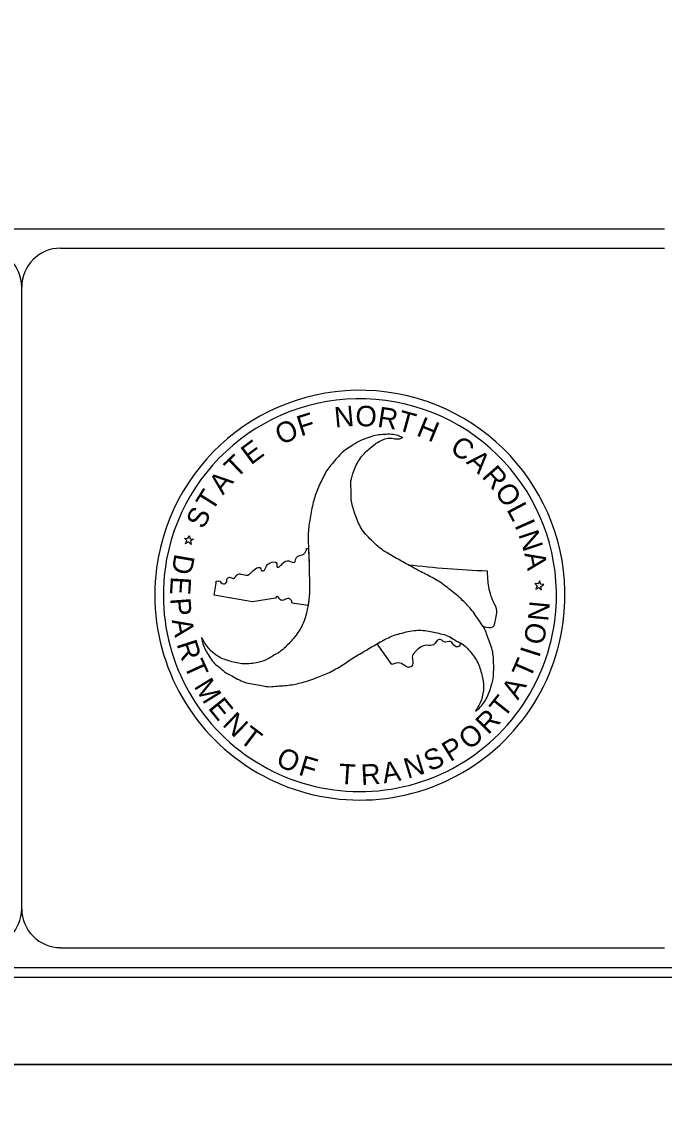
# Model space of a CAD drawing. Extents: x 925297 to 940193, y 663541 to 689899.
# Drawn here: x 937191 to 938513, y 681019 to 683245 of the extents above; entities that cross this region are included whole.
import ezdxf

# ---------------------------------------------------------------- set-up
doc = ezdxf.new("R2010")
doc.units = 0
for name, color, linetype in [('Sheet Cutting Line CELL', 7, 'Continuous'), ('Sheet Plot Border Inside CELL', 7, 'Continuous'), ('Sheet Plot Border Outside CELL', 7, 'Continuous'), ('Sheet Title CELL', 7, 'Continuous')]:
    doc.layers.add(name, color=color, linetype=linetype)

msp = doc.modelspace()

# ---------------------------------------------------------------- linework, layer by layer
at = {"layer": 'Sheet Cutting Line CELL'}
msp.add_line((925296.7, 681098.7), (938768.7, 681098.7), dxfattribs=at)
at = {"layer": 'Sheet Plot Border Inside CELL'}
msp.add_lwpolyline([(925400.7, 681278.2), (938732.7, 681278.2), (938732.7, 689719), (925400.7, 689719)], close=True, dxfattribs=at)
at = {"layer": 'Sheet Plot Border Outside CELL'}
for points in [[(938768.7, 689898.6), (925296.7, 689898.6), (925296.7, 681098.7), (938768.7, 681098.7)], [(925296.7, 672338.7), (938764.7, 672338.7), (938764.7, 681098.7), (925296.7, 681098.7)]]:
    msp.add_lwpolyline(points, close=True, dxfattribs=at)
at = {"layer": 'Sheet Title CELL'}
for p, q in [((927152.7, 682818.7), (938512.7, 682818.7)), ((937270.9, 682778.7), (938512.7, 682778.7)), ((937190.9, 681418.7), (937190.9, 682698.7)), ((937974.9, 682389.9), (937974, 682389.1)), ((937974.9, 682389.9), (937974, 682389.1)), ((937530.7, 682177.1), (937525.5, 682182.2)), ((937525.5, 682182.2), (937532.8, 682181.3)), ((937527.7, 682170.5), (937530.7, 682177.1)), ((937533.8, 682174.1), (937527.7, 682170.5)), ((937532.8, 682181.3), (937535.7, 682187.7)), ((937539.2, 682168.9), (937533.8, 682174.1)), ((937535.7, 682187.7), (937537.2, 682180.7)), ((937537.2, 682180.7), (937544.4, 682179.7)), ((937544.4, 682179.7), (937537.9, 682176.2)), ((937537.9, 682176.2), (937539.2, 682168.9)), ((937985.5, 682127.2), (937985.5, 682127.2)), ((937586.7, 682064.5), (937590.9, 682089.5)), ((938253.2, 682087.8), (938246.1, 682088.7)), ((938246.1, 682088.7), (938251.4, 682083.7)), ((938251.4, 682083.7), (938248.4, 682077.1)), ((938248.4, 682077.1), (938254.6, 682080.6)), ((938256.4, 682094.2), (938253.2, 682087.8)), ((938254.6, 682080.6), (938259.8, 682075.6)), ((938258, 682087.2), (938256.4, 682094.2)), ((938265, 682086.5), (938258, 682087.2)), ((938258.6, 682082.8), (938265, 682086.5)), ((938259.8, 682075.6), (938258.6, 682082.8)), ((937665.6, 682051), (937586.7, 682064.5)), ((937712.9, 682058.3), (937665.6, 682051)), ((937780.2, 682043.7), (937747.1, 682048.5)), ((938304.6, 682009.1), (938304.6, 682009.1)), ((937952.1, 681922.1), (937922.1, 681964.8)), ((937922.1, 681964.8), (937922.1, 681964.8))]:
    msp.add_line(p, q, dxfattribs=at)
for points in [[(937270.9, 681338.7), (938512.7, 681338.7)], [(926712.7, 681298.6), (938552.7, 681298.6)]]:
    msp.add_lwpolyline(points, dxfattribs=at)
for centre, radius, start, end in [((937110.9, 682698.7), 80, 0, 90), ((937270.9, 682698.7), 80, 90, 180), ((937886.5, 682064.6), 421.7, 352.4211, 172.4211), ((937886.5, 682064.6), 404.2, 352.4211, 172.4211), ((938235.7, 684336.7), 2223.6, 258.0996, 258.1992), ((938235.7, 684336.7), 2223.6, 263.5387, 267.7447), ((937886.5, 682064.6), 421.7, 172.4211, 352.4211), ((937886.5, 682064.6), 404.2, 172.4211, 352.4211), ((937110.9, 681419.2), 80, 270, 360), ((937270.9, 681419.2), 80, 180, 270)]:
    msp.add_arc(centre, radius, start, end, dxfattribs=at)
for points in [[(937974, 682389.1), (937965, 682392.9), (937937.1, 682395.4), (937907.6, 682390.1), (937904.9, 682389.1), (937889.8, 682383.6), (937873.4, 682374.4), (937847.8, 682356), (937827, 682331.9), (937818.5, 682321.5), (937811.6, 682308.3), (937798.4, 682280.1), (937789.8, 682252.2), (937783.5, 682219.1), (937780.1, 682189.8), (937780.9, 682159.3), (937782.1, 682128.5), (937782.6, 682098.7), (937782.7, 682068.1), (937778.8, 682038.2), (937778.3, 682035.6), (937768.8, 682004.5), (937752.2, 681978.3), (937732.5, 681957.1), (937721.2, 681947.6), (937705.8, 681938.6), (937697, 681933.3), (937676.8, 681926.2), (937647.3, 681923.3), (937619.5, 681928.6), (937595.5, 681938.2), (937575.6, 681955.1), (937561, 681977.5)], [(938124.3, 681825.8), (938131.6, 681831.6), (938148.1, 681854.5), (938158.2, 681882.7), (938159, 681885.5), (938161.4, 681901.4), (938161.7, 681920.4), (938158.8, 681951.7), (938148.1, 681981.6), (938143.6, 681994.2), (938135.4, 682007), (938117.6, 682032.4), (938097.9, 682053.9), (938072.3, 682075.7), (938048.5, 682093.1), (938021.6, 682108), (937994.5, 682122.2), (937968.7, 682136.6), (937941.6, 682152.1), (937917.9, 682170.2), (937916, 682172.1), (937893.5, 682196.1), (937879.3, 682223.6), (937870.6, 682251.1), (937868.4, 682265.3), (937868.3, 682283.4), (937867.8, 682293.8), (937872.1, 682314.7), (937884.3, 682341.9), (937902.6, 682363.1), (937923, 682378.9), (937947.8, 682387.7), (937974, 682389.1), (937974.9, 682389.9)], [(937590.9, 682089.5), (937590.4, 682092), (937595, 682094.2), (937606.1, 682087.8), (937612.7, 682092.1), (937613.1, 682097.2), (937618.5, 682101.6), (937626.4, 682098.9), (937634.9, 682107.3), (937641.8, 682108), (937655.9, 682106.1), (937674.9, 682120.7), (937682.1, 682120.8), (937683.2, 682116.1), (937687.5, 682114.6), (937696.5, 682127.6), (937698.6, 682129.3), (937712.5, 682132.8), (937715.6, 682129.8), (937715.8, 682123.5), (937717.5, 682122), (937722.2, 682124.5), (937729, 682131.2), (937740.5, 682135.3), (937752.6, 682132.2), (937756, 682142), (937771.7, 682149.7), (937775.5, 682155.1), (937777, 682161)], [(937780.9, 682160.1), (937780.9, 682159.3), (937782.1, 682128.5), (937782.6, 682098.7), (937782.7, 682068.1), (937780, 682043.7)], [(938141.1, 681999.1), (938135.4, 682007), (938117.6, 682032.4), (938097.9, 682053.9), (938072.3, 682075.7), (938048.5, 682093.1), (938021.6, 682108), (937994.5, 682122.2), (937985.5, 682127.2)], [(938148.1, 682114.8), (938150.4, 682086.1), (938160.6, 682051.3), (938167.7, 682032.1), (938165.3, 682016.6), (938159.3, 681998.7), (938141.2, 681999.2)], [(937747.1, 682048.5), (937744.7, 682055), (937738.5, 682057.7), (937729.2, 682054.2), (937722.7, 682055.5), (937716.2, 682061.6), (937712.9, 682058.3)], [(937561, 681977.5), (937562.7, 681967.7), (937574.4, 681942.2), (937593.5, 681919.2), (937595.7, 681917.7), (937608.3, 681907), (937624.4, 681897.6), (937653.2, 681884.4), (937684.2, 681878.8), (937697.4, 681876.4), (937713, 681877.1), (937743.4, 681879.8), (937771.7, 681886), (937803.7, 681897.3), (937830.5, 681909), (937856.8, 681925), (937882.7, 681941.6), (937908.4, 681956.7), (937935.1, 681972), (937962.7, 681983.8), (937965.7, 681984.6), (937997.5, 681991.9), (938028.1, 681990.6), (938056, 681984.4), (938070.3, 681979.3), (938085.4, 681970.2), (938095, 681965.5), (938110.9, 681951.4), (938128, 681927.3), (938137.3, 681900.8), (938140.9, 681875), (938136.3, 681849.3), (938124.3, 681825.8)], [(937922.1, 681964.8), (937935.1, 681972), (937962.7, 681983.8), (937965.7, 681984.6), (937997.5, 681991.9), (938028.1, 681990.6), (938056, 681984.4), (938070.3, 681979.3), (938085.4, 681970.2), (938094.3, 681965.7)], [(938094.1, 681965.6), (938089.3, 681958.8), (938082.9, 681959.1), (938073.1, 681969.4), (938059.2, 681968.5), (938053.5, 681972.9), (938049.4, 681973.6), (938038, 681962.6), (938024.2, 681961.4), (938000.4, 681948.3), (937994.7, 681939.6), (937993.6, 681919.3), (937987.8, 681916.1), (937981.5, 681917.9), (937968.8, 681924.9), (937952.1, 681922.1)]]:
    msp.add_spline(points, degree=3, dxfattribs=at)

# ---------------------------------------------------------------- texts
for s, height, rotation, p in [('F', 42.1, 17.4918, (937764.9, 682391.1)), ('N', 42.1, 5.4049, (937835.7, 682409.3)), ('O', 42.2, 357.9068, (937876.7, 682412.9)), ('R', 42.1, 351.2969, (937921.1, 682411.3)), ('T', 42.2, 344.6472, (937960.9, 682405.2)), ('O', 42.1, 24.6387, (937724.3, 682372.8)), ('H', 42, 337.5625, (938000.6, 682394)), ('E', 41.9, 36.5781, (937662.3, 682331.4)), ('C', 41.9, 325.2202, (938069.4, 682361.4)), ('T', 42, 43.6937, (937632.5, 682303)), ('A', 42, 317.7231, (938103.7, 682337.3)), ('R', 42, 311.3592, (938135.7, 682308.3)), ('A', 42.2, 50.7489, (937604.9, 682269.4)), ('T', 42.1, 57.8012, (937582.5, 682234.9)), ('O', 42.1, 304.2396, (938162.2, 682278.1)), ('S', 42, 64.1774, (937565, 682198.9)), ('L', 41.9, 298.0059, (938187.4, 682241.1)), ('I', 42.1, 294.0166, (938203.7, 682208.6)), ('N', 42, 288.3165, (938211.8, 682189.8)), ('D', 42.1, 260.2741, (937505.7, 682151.3)), ('A', 42.1, 280.8845, (938224.5, 682150.5)), ('E', 41.9, 266.562, (937498, 682103.7)), ('P', 42.1, 274.0944, (937496.1, 682058)), ('N', 42.1, 84.6293, (938273.7, 682009.7)), ('A', 42, 280.687, (937499.3, 682013.2)), ('O', 41.9, 77.3812, (938263.1, 681960)), ('R', 42, 287.7556, (937509.1, 681964.4)), ('I', 42.2, 72.2456, (938255.1, 681934.2)), ('T', 42, 294.4062, (937523.7, 681920.3)), ('T', 42, 66.5957, (938236.5, 681890.5)), ('M', 41.9, 301.6412, (937544, 681877.1)), ('A', 42.1, 59.5113, (938211.7, 681847.3)), ('T', 41.9, 51.4242, (938182.6, 681809.6)), ('E', 41.9, 309.108, (937572.8, 681832.1)), ('N', 42.1, 316.0795, (937601.8, 681797.2)), ('R', 42.1, 45.3245, (938150.2, 681776)), ('T', 42, 322.9215, (937636.4, 681764.6)), ('O', 42.1, 38.1354, (938110.5, 681744.4)), ('P', 42, 31.4434, (938072.2, 681720.6)), ('O', 42, 336.2252, (937711.4, 681715.4)), ('S', 41.9, 24.2515, (938029.9, 681701.2)), ('F', 42, 343.3904, (937758.2, 681695.5)), ('N', 41.9, 17.041, (937984.7, 681686.5)), ('T', 41.9, 356.2997, (937842, 681676.3)), ('R', 42.1, 3.2563, (937889.6, 681673.8)), ('A', 41.9, 10.0094, (937935.9, 681677.1))]:
    msp.add_text(s, height=height, rotation=rotation, dxfattribs=at).set_placement(p)

doc.saveas('drawing.dxf')
